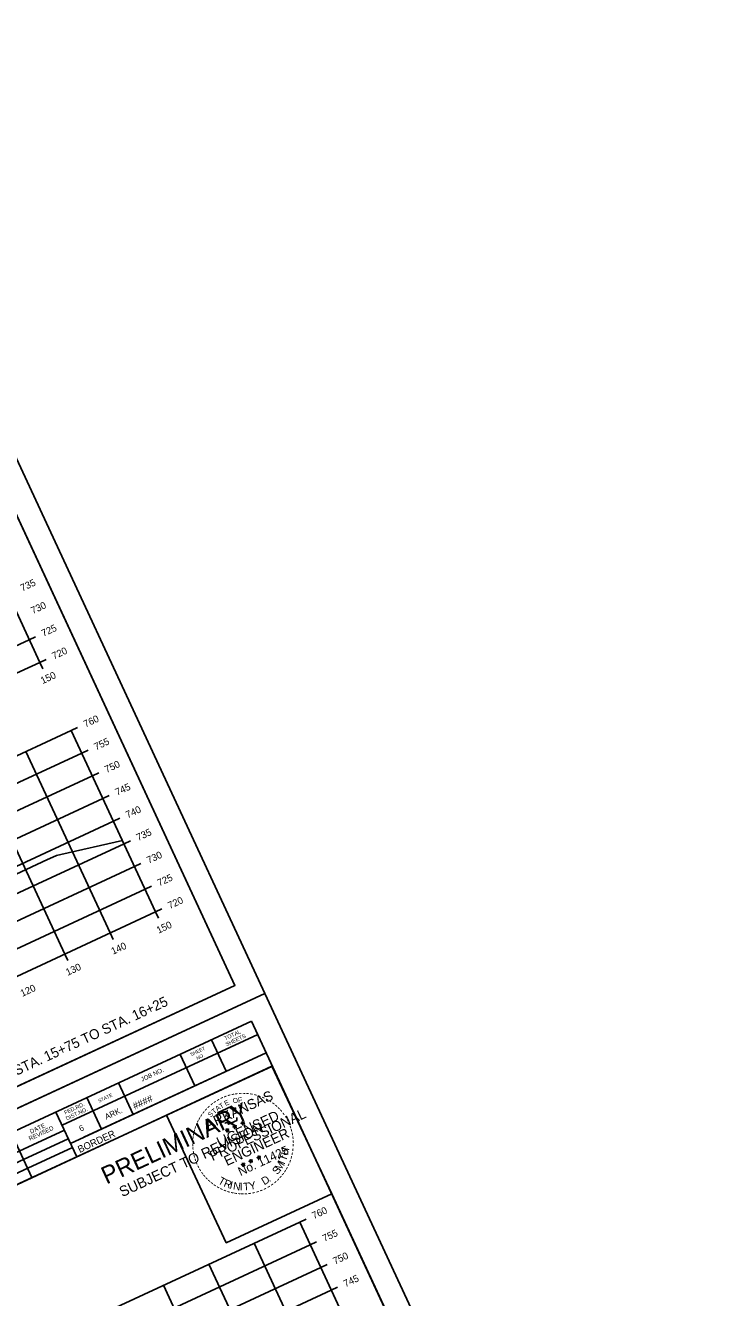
# Model space of a CAD drawing. Extents: x 1354696 to 1366163, y 660729 to 670380.
# Drawn here: x 1358937.5 to 1359075.2, y 666178.8 to 666433.1 of the extents above; entities that cross this region are included whole.
import ezdxf

# ---------------------------------------------------------------- set-up
doc = ezdxf.new("R2010")
doc.units = 0
for name, color, linetype in [('R_Axis', 7, 'Continuous'), ('R_Axis Annot', 7, 'Continuous'), ('R_Border', 7, 'Continuous'), ('R_Border PE', 7, 'Continuous'), ('R_Border Prem', 7, 'Continuous'), ('R_Draft', 7, 'Continuous'), ('R_Exist Surface', 7, 'Continuous'), ('R_Grid', 7, 'Continuous'), ('R_No Plot', 7, 'Continuous')]:
    doc.layers.add(name, color=color, linetype=linetype)

msp = doc.modelspace()

# ---------------------------------------------------------------- linework, layer by layer
at = {"layer": 'R_Axis'}
for p, q in [((1358940.34, 666305.76), (1358921.39, 666346.57)), ((1358939.5, 666310.88), (1358938.23, 666310.29)), ((1358668.23, 666179.43), (1358940.34, 666305.76)), ((1358941.61, 666306.35), (1358940.34, 666305.76)), ((1358940.93, 666304.49), (1358940.34, 666305.76)), ((1358947.92, 666292.74), (1358946.65, 666292.15)), ((1358963.5, 666255.87), (1358946.65, 666292.15)), ((1358950.03, 666288.21), (1358948.76, 666287.62)), ((1358952.14, 666283.67), (1358950.87, 666283.08)), ((1358954.24, 666279.14), (1358952.97, 666278.55)), ((1358956.35, 666274.6), (1358955.08, 666274.01)), ((1358958.45, 666270.07), (1358957.18, 666269.48)), ((1358960.56, 666265.53), (1358959.29, 666264.94)), ((1358962.66, 666261), (1358961.39, 666260.41)), ((1358964.77, 666256.46), (1358963.5, 666255.87)), ((1358691.39, 666129.54), (1358963.5, 666255.87)), ((1358964.09, 666254.6), (1358963.5, 666255.87)), ((1358955.02, 666250.39), (1358954.43, 666251.66)), ((1358945.95, 666246.18), (1358945.36, 666247.45)), ((1358993.55, 666194.48), (1358992.28, 666193.89)), ((1359009.12, 666157.61), (1358992.28, 666193.89)), ((1358995.65, 666189.94), (1358994.38, 666189.35)), ((1358997.76, 666185.41), (1358996.49, 666184.82)), ((1358999.86, 666180.87), (1358998.59, 666180.28))]:
    msp.add_line(p, q, dxfattribs=at)
at = {"layer": 'R_Border'}
for p, q in [((1358979.34, 666241.18), (1358892.82, 666427.53)), ((1358979.34, 666241.18), (1358692.56, 666108.03)), ((1358695.88, 666100.89), (1358982.66, 666234.03)), ((1359069.18, 666047.68), (1358982.66, 666234.03)), ((1358983.9, 666231.37), (1358944.8, 666213.22)), ((1358983.89, 666231.38), (1358983.89, 666231.38)), ((1358974.68, 666230.33), (1358977.6, 666224.03)), ((1358985.58, 666227.74), (1358946.49, 666209.59)), ((1358949.17, 666210.83), (1358985.58, 666227.74)), ((1358968.38, 666227.4), (1358971.3, 666221.11)), ((1358986.82, 666225.07), (1358930, 666198.69)), ((1358956.06, 666221.69), (1358958.99, 666215.39)), ((1358949.77, 666218.76), (1358952.69, 666212.47)), ((1358943.57, 666215.88), (1358947.73, 666206.92)), ((1358927.53, 666204.01), (1358945.26, 666212.24)), ((1358938.78, 666202.77), (1358934.62, 666211.73)), ((1358928.32, 666202.32), (1358946.04, 666210.55)), ((1358929.14, 666200.56), (1358946.86, 666208.79))]:
    msp.add_line(p, q, dxfattribs=at)
at = {"layer": 'R_Border PE'}
for p, q in [((1358979.34, 666212.94), (1358979.18, 666213.27)), ((1358979.18, 666213.27), (1358979.33, 666213.06)), ((1358979.18, 666213.27), (1358979.25, 666213.02)), ((1358979.6, 666213.18), (1358979.34, 666212.94)), ((1358979.6, 666213.18), (1358979.37, 666213.02)), ((1358979.6, 666213.18), (1358979.46, 666213)), ((1358980.58, 666213.62), (1358980.83, 666213.69)), ((1358980.58, 666213.62), (1358980.94, 666213.67)), ((1358980.58, 666213.62), (1358980.84, 666213.61)), ((1358980.94, 666213.67), (1358980.79, 666214)), ((1358980.79, 666214), (1358980.94, 666213.79)), ((1358980.79, 666214), (1358980.86, 666213.75)), ((1358980.87, 666213.31), (1358980.94, 666213.67)), ((1358980.87, 666213.31), (1358980.97, 666213.59)), ((1358980.87, 666213.31), (1358980.88, 666213.58)), ((1358981.21, 666213.91), (1358980.94, 666213.67)), ((1358981.26, 666213.49), (1358980.94, 666213.67)), ((1358981.21, 666213.91), (1358980.97, 666213.75)), ((1358981.26, 666213.49), (1358980.97, 666213.59)), ((1358981.26, 666213.49), (1358981.01, 666213.69)), ((1358981.21, 666213.91), (1358981.07, 666213.74)), ((1358977.46, 666212.19), (1358977.71, 666212.25)), ((1358977.46, 666212.19), (1358977.82, 666212.23)), ((1358977.46, 666212.19), (1358977.72, 666212.18)), ((1358977.82, 666212.23), (1358977.67, 666212.56)), ((1358977.67, 666212.56), (1358977.82, 666212.36)), ((1358977.67, 666212.56), (1358977.74, 666212.32)), ((1358977.75, 666211.87), (1358977.82, 666212.23)), ((1358977.75, 666211.87), (1358977.85, 666212.16)), ((1358977.75, 666211.87), (1358977.76, 666212.15)), ((1358978.09, 666212.48), (1358977.82, 666212.23)), ((1358978.14, 666212.05), (1358977.82, 666212.23)), ((1358978.09, 666212.48), (1358977.85, 666212.31)), ((1358978.14, 666212.05), (1358977.85, 666212.16)), ((1358978.14, 666212.05), (1358977.89, 666212.26)), ((1358978.09, 666212.48), (1358977.95, 666212.3)), ((1358978.97, 666212.89), (1358979.22, 666212.96)), ((1358978.97, 666212.89), (1358979.34, 666212.94)), ((1358978.97, 666212.89), (1358979.24, 666212.88)), ((1358979.27, 666212.58), (1358979.34, 666212.94)), ((1358979.27, 666212.58), (1358979.37, 666212.86)), ((1358979.27, 666212.58), (1358979.28, 666212.85)), ((1358979.65, 666212.76), (1358979.34, 666212.94)), ((1358979.65, 666212.76), (1358979.37, 666212.86)), ((1358979.65, 666212.76), (1358979.41, 666212.96)), ((1358981.01, 666205.36), (1358980.85, 666205.69)), ((1358980.85, 666205.69), (1358981, 666205.49)), ((1358980.85, 666205.69), (1358980.92, 666205.45)), ((1358981.27, 666205.61), (1358981.01, 666205.36)), ((1358981.27, 666205.61), (1358981.04, 666205.44)), ((1358981.27, 666205.61), (1358981.13, 666205.43)), ((1358982.16, 666206.02), (1358982.41, 666206.08)), ((1358982.16, 666206.02), (1358982.52, 666206.07)), ((1358982.16, 666206.02), (1358982.42, 666206.01)), ((1358982.52, 666206.07), (1358982.37, 666206.4)), ((1358982.37, 666206.4), (1358982.52, 666206.19)), ((1358982.37, 666206.4), (1358982.44, 666206.15)), ((1358982.45, 666205.7), (1358982.52, 666206.07)), ((1358982.45, 666205.7), (1358982.55, 666205.99)), ((1358982.45, 666205.7), (1358982.46, 666205.98)), ((1358982.79, 666206.31), (1358982.52, 666206.07)), ((1358982.84, 666205.89), (1358982.52, 666206.07)), ((1358982.79, 666206.31), (1358982.55, 666206.15)), ((1358982.84, 666205.89), (1358982.55, 666205.99)), ((1358982.84, 666205.89), (1358982.59, 666206.09)), ((1358982.79, 666206.31), (1358982.65, 666206.13)), ((1358983.76, 666206.75), (1358984.01, 666206.82)), ((1358983.76, 666206.75), (1358984.13, 666206.8)), ((1358983.76, 666206.75), (1358984.03, 666206.74)), ((1358984.13, 666206.8), (1358983.97, 666207.13)), ((1358983.97, 666207.13), (1358984.12, 666206.93)), ((1358983.97, 666207.13), (1358984.04, 666206.89)), ((1358984.06, 666206.44), (1358984.13, 666206.8)), ((1358984.06, 666206.44), (1358984.16, 666206.73)), ((1358984.06, 666206.44), (1358984.07, 666206.71)), ((1358984.4, 666207.05), (1358984.13, 666206.8)), ((1358984.45, 666206.62), (1358984.13, 666206.8)), ((1358984.4, 666207.05), (1358984.16, 666206.88)), ((1358984.45, 666206.62), (1358984.16, 666206.72)), ((1358984.45, 666206.62), (1358984.2, 666206.83)), ((1358984.4, 666207.05), (1358984.25, 666206.87)), ((1358980.64, 666205.32), (1358980.89, 666205.38)), ((1358980.64, 666205.32), (1358981.01, 666205.36)), ((1358980.64, 666205.32), (1358980.91, 666205.31)), ((1358980.94, 666205), (1358981.01, 666205.36)), ((1358980.94, 666205), (1358981.04, 666205.29)), ((1358980.94, 666205), (1358980.95, 666205.28)), ((1358981.32, 666205.18), (1358981.01, 666205.36)), ((1358981.32, 666205.18), (1358981.04, 666205.29)), ((1358981.32, 666205.18), (1358981.08, 666205.39))]:
    msp.add_line(p, q, dxfattribs=at)
for points in [[(1358979.43, 666216.36), (1358979.44, 666216.68), (1358978.83, 666216.37), (1358978.69, 666217.03), (1358975.86, 666215.72)], [(1358975.86, 666215.72), (1358976.45, 666215.08)], [(1358977.33, 666213.73), (1358977.37, 666213.65), (1358977.88, 666213.87), (1358978.03, 666213.42), (1358979.73, 666214.21), (1358979.69, 666214.78)], [(1358979.18, 666213.27), (1358979.65, 666212.76), (1358978.97, 666212.89), (1358979.6, 666213.18), (1358979.27, 666212.58), (1358979.18, 666213.27)], [(1358980.79, 666214), (1358981.26, 666213.49), (1358980.58, 666213.62), (1358981.21, 666213.91), (1358980.87, 666213.31), (1358980.79, 666214)], [(1358977.67, 666212.56), (1358978.14, 666212.05), (1358977.46, 666212.19), (1358978.09, 666212.48), (1358977.75, 666211.87), (1358977.67, 666212.56)], [(1358980.85, 666205.69), (1358981.32, 666205.18), (1358980.64, 666205.32), (1358981.27, 666205.61), (1358980.94, 666205), (1358980.85, 666205.69)], [(1358982.37, 666206.4), (1358982.84, 666205.89), (1358982.16, 666206.02), (1358982.79, 666206.31), (1358982.45, 666205.7), (1358982.37, 666206.4)], [(1358983.97, 666207.13), (1358984.45, 666206.62), (1358983.76, 666206.75), (1358984.4, 666207.05), (1358984.06, 666206.44), (1358983.97, 666207.13)]]:
    msp.add_lwpolyline(points, dxfattribs=at)
for centre, radius in [((1358980.94, 666213.67), 0.172), ((1358980.94, 666213.67), 0.145), ((1358980.94, 666213.67), 0.116), ((1358980.94, 666213.67), 0.0991), ((1358980.94, 666213.67), 0.0747), ((1358980.94, 666213.67), 0.0495), ((1358980.94, 666213.67), 0.0296), ((1358977.82, 666212.23), 0.172), ((1358977.82, 666212.23), 0.145), ((1358977.82, 666212.23), 0.116), ((1358977.82, 666212.23), 0.0991), ((1358977.82, 666212.23), 0.0747), ((1358977.82, 666212.23), 0.0495), ((1358977.82, 666212.23), 0.0296), ((1358979.34, 666212.93), 0.172), ((1358979.34, 666212.93), 0.145), ((1358979.34, 666212.93), 0.116), ((1358979.34, 666212.93), 0.0991), ((1358979.34, 666212.93), 0.0747), ((1358979.34, 666212.93), 0.0495), ((1358979.34, 666212.93), 0.0296), ((1358981.01, 666205.36), 0.172), ((1358982.52, 666206.06), 0.172), ((1358982.52, 666206.06), 0.145), ((1358982.52, 666206.06), 0.116), ((1358982.52, 666206.06), 0.0991), ((1358982.52, 666206.06), 0.0747), ((1358982.52, 666206.06), 0.0495), ((1358982.52, 666206.06), 0.0296), ((1358984.13, 666206.8), 0.172), ((1358984.13, 666206.8), 0.145), ((1358984.13, 666206.8), 0.116), ((1358984.13, 666206.8), 0.0991), ((1358984.13, 666206.8), 0.0747), ((1358984.13, 666206.8), 0.0495), ((1358984.13, 666206.8), 0.0296), ((1358981.01, 666205.36), 0.145), ((1358981.01, 666205.36), 0.116), ((1358981.01, 666205.36), 0.0991), ((1358981.01, 666205.36), 0.0747), ((1358981.01, 666205.36), 0.0495), ((1358981.01, 666205.36), 0.0296)]:
    msp.add_circle(centre, radius, dxfattribs=at)
at = {"layer": 'R_Exist Surface'}
msp.add_lwpolyline([(1358906.25, 666249.72), (1358939.75, 666265.33), (1358941.87, 666266.33), (1358942.93, 666266.81), (1358943.66, 666267.14), (1358944.56, 666267.37), (1358956.86, 666270.18)], dxfattribs=at)
at = {"layer": 'R_Grid'}
for p, q in [((1358940.34, 666305.76), (1358921.39, 666346.57)), ((1358666.13, 666183.96), (1358938.23, 666310.29)), ((1358668.23, 666179.43), (1358940.34, 666305.76)), ((1358674.55, 666165.82), (1358946.65, 666292.15)), ((1358963.5, 666255.87), (1358946.65, 666292.15)), ((1358676.66, 666161.29), (1358948.76, 666287.62)), ((1358954.43, 666251.66), (1358937.58, 666287.94)), ((1358678.76, 666156.75), (1358950.87, 666283.08)), ((1358945.36, 666247.45), (1358928.51, 666283.73)), ((1358680.87, 666152.22), (1358952.97, 666278.55)), ((1358682.97, 666147.68), (1358955.08, 666274.01)), ((1358685.08, 666143.15), (1358957.18, 666269.48)), ((1358687.18, 666138.61), (1358959.29, 666264.94)), ((1358689.29, 666134.08), (1358961.39, 666260.41)), ((1358691.39, 666129.54), (1358963.5, 666255.87)), ((1358720.17, 666067.56), (1358992.28, 666193.89)), ((1359009.12, 666157.61), (1358992.28, 666193.89)), ((1358722.28, 666063.02), (1358994.38, 666189.35)), ((1359000.05, 666153.4), (1358983.21, 666189.68)), ((1358990.98, 666149.19), (1358974.14, 666185.47)), ((1358724.38, 666058.49), (1358996.49, 666184.82)), ((1358726.49, 666053.95), (1358998.59, 666180.28)), ((1358981.91, 666144.98), (1358965.07, 666181.26))]:
    msp.add_line(p, q, dxfattribs=at)
at = {"layer": 'R_No Plot'}
for p, q in [((1358682.99, 666099.2), (1358985.33, 666239.57)), ((1358682.99, 666099.2), (1358985.33, 666239.57)), ((1358974.54, 666194.61), (1358974.54, 666194.61))]:
    msp.add_line(p, q, dxfattribs=at)
for points in [[(1358593.15, 666292.7), (1358895.49, 666433.07), (1358985.33, 666239.57), (1358682.98, 666099.2)], [(1358818.21, 666392.89), (1358836.01, 666401.15), (1358840.17, 666392.19), (1358854.78, 666398.98), (1358875.82, 666408.75), (1358887.79, 666383.26), (1358908.84, 666393.03), (1358979.34, 666241.18), (1358692.56, 666108.03), (1358606.04, 666294.39)], [(1358682.98, 666099.2), (1358985.33, 666239.57), (1359075.16, 666046.07), (1358772.82, 665905.7)], [(1358965.66, 666215.25), (1358986.71, 666225.02), (1358998.67, 666199.53), (1358977.62, 666189.76)], [(1358908.05, 666199.39), (1358925.84, 666207.65), (1358930, 666198.69), (1358944.62, 666205.48), (1358965.66, 666215.25), (1358977.62, 666189.76), (1358998.67, 666199.53), (1359069.18, 666047.68), (1358782.4, 665914.53), (1358695.88, 666100.89)]]:
    msp.add_lwpolyline(points, close=True, dxfattribs=at)

# ---------------------------------------------------------------- texts
at = {"layer": 'R_Axis Annot'}
for s, p in [('735', (1358936.86, 666319.91)), ('730', (1358938.96, 666315.37)), ('725', (1358941.07, 666310.84)), ('720', (1358943.17, 666306.3)), ('150', (1358940.91, 666301.39)), ('760', (1358949.49, 666292.7)), ('755', (1358951.59, 666288.16)), ('750', (1358953.7, 666283.63)), ('745', (1358955.81, 666279.09)), ('740', (1358957.91, 666274.56)), ('735', (1358960.02, 666270.02)), ('730', (1358962.12, 666265.49)), ('725', (1358964.23, 666260.95)), ('720', (1358966.33, 666256.42)), ('150', (1358964.07, 666251.51)), ('140', (1358955, 666247.3)), ('130', (1358945.93, 666243.09)), ('120', (1358936.86, 666238.88)), ('760', (1358995.11, 666194.43)), ('755', (1358997.22, 666189.9)), ('750', (1358999.32, 666185.36)), ('745', (1359001.43, 666180.83))]:
    msp.add_text(s, height=1.4, rotation=24.9042, dxfattribs=at).set_placement(p)
at = {"layer": 'R_Border'}
for s, height, p in [('TOTAL', 0.782, (1358977.43, 666230.19)), ('SHEETS', 0.782, (1358977.67, 666229)), ('SHEET', 0.684, (1358970.61, 666227.03)), ('NO.', 0.684, (1358971.81, 666226.28)), ('JOB NO.', 0.879, (1358960.8, 666221.94)), ('STATE', 0.684, (1358952.19, 666217.73)), ('####', 1.4, (1358959.31, 666216.35)), ('FED.RD.', 0.782, (1358945.45, 666215.34)), ('DIST.NO.', 0.782, (1358945.76, 666214.19)), ('ARK.', 1.172, (1358953.67, 666214.31)), ('DATE', 0.879, (1358938.6, 666211.52)), ('6', 1.17, (1358948.53, 666211.93)), ('REVISED', 0.879, (1358938.39, 666210.12)), ('BORDER', 1.4, (1358948.33, 666207.68))]:
    msp.add_text(s, height=height, rotation=24.9042, dxfattribs=at).set_placement(p)
at = {"layer": 'R_Border PE'}
for s, height, rotation, p in [('ARKANSAS', 2, 24.9042, (1358973.97, 666212.32)), ('-', 1.6, 30.801, (1358975.99, 666217.59)), ('-', 1.6, 25.0904, (1358976.66, 666217.98)), ('-', 1.6, 22.6472, (1358977.32, 666218.27)), ('E', 1, 25.7365, (1358977.49, 666217.07)), ('-', 1.6, 17.0659, (1358978.02, 666218.54)), ('-', 1.6, 12.1091, (1358978.72, 666218.73)), ('O', 1, 15.3557, (1358979.04, 666217.56)), ('-', 1.6, 7.2404, (1358979.36, 666218.86)), ('F', 1, 4.9748, (1358980, 666217.75)), ('-', 1.6, 2.7593, (1358980.12, 666218.97)), ('-', 1.6, 359.0253, (1358980.81, 666218.99)), ('-', 1.6, 354.5451, (1358981.45, 666218.98)), ('-', 1.6, 350.7668, (1358982.19, 666218.92)), ('-', 1.6, 345.4339, (1358982.92, 666218.79)), ('-', 1.6, 340.4828, (1358983.67, 666218.6)), ('-', 1.6, 334.7839, (1358984.42, 666218.34)), ('-', 1.6, 331.5563, (1358985.15, 666218.01)), ('-', 1.6, 53.696, (1358973.35, 666215.15)), ('-', 1.6, 49.2114, (1358973.79, 666215.71)), ('-', 1.6, 44.0802, (1358974.25, 666216.22)), ('S', 1, 46.4982, (1358974.51, 666214.74)), ('PROFESSIONAL', 2, 24.9042, (1358974.86, 666206.06)), ('-', 1.6, 38.5343, (1358974.83, 666216.75)), ('T', 1, 41.3078, (1358975.2, 666215.42)), ('-', 1.6, 35.1235, (1358975.38, 666217.18)), ('A', 1, 36.1173, (1358975.84, 666216)), ('LICENSED', 2, 24.9042, (1358976.26, 666208.81)), ('T', 1, 30.9269, (1358976.54, 666216.5)), ('-', 1.4, 328.5795, (1358985.83, 666217.7)), ('-', 1.6, 324.5725, (1358986.37, 666217.29)), ('-', 1.6, 319.567, (1358986.93, 666216.87)), ('-', 1.6, 315.477, (1358987.4, 666216.45)), ('-', 1.6, 310.0274, (1358987.86, 666216.03)), ('-', 1.6, 305.4535, (1358988.35, 666215.44)), ('-', 1.6, 67.8664, (1358972.12, 666212.86)), ('-', 1.6, 63.8548, (1358972.33, 666213.42)), ('-', 1.6, 61.1359, (1358972.61, 666213.96)), ('-', 1.6, 58.9677, (1358972.96, 666214.56)), ('DWB', 0.01, 24.9042, (1358980.93, 666213.66)), ('-', 1.6, 301.5003, (1358988.82, 666214.81)), ('-', 1.6, 299.2343, (1358989.18, 666214.18)), ('-', 1.6, 294.8448, (1358989.48, 666213.62)), ('-', 1.6, 82.9748, (1358971.54, 666210.32)), ('-', 1.6, 79.1366, (1358971.61, 666210.94)), ('-', 1.6, 75.5183, (1358971.75, 666211.63)), ('-', 1.6, 73.3272, (1358971.91, 666212.24)), ('ENGINEER', 2, 24.9042, (1358977.74, 666205.06)), ('DWB', 0.01, 24.9042, (1358977.81, 666212.22)), ('DWB', 0.01, 24.9042, (1358979.33, 666212.93)), ('-', 1.6, 288.4214, (1358989.74, 666213.01)), ('-', 1.6, 285.8995, (1358989.95, 666212.39)), ('-', 1.6, 280.6668, (1358990.14, 666211.72)), ('-', 1.6, 277.7723, (1358990.28, 666211)), ('-', 1.6, 92.6784, (1358971.54, 666208.97)), ('-', 1.6, 87.7755, (1358971.52, 666209.63)), ('-', 1.6, 97.2986, (1358971.61, 666208.31)), ('-', 1.6, 100.3651, (1358971.73, 666207.58)), ('No. 11425', 1.757, 24.9042, (1358980.46, 666203.06)), ('H', 1.54, 79.513, (1358989.96, 666207.17)), ('-', 1.6, 263.9754, (1358990.34, 666208.76)), ('-', 1.6, 272.7928, (1358990.36, 666210.29)), ('-', 1.6, 269.5239, (1358990.38, 666209.61)), ('-', 1.6, 106.1054, (1358971.91, 666206.87)), ('-', 1.6, 110.0905, (1358972.13, 666206.22)), ('-', 1.6, 113.9664, (1358972.4, 666205.57)), ('DWB', 0.01, 24.9042, (1358982.51, 666206.06)), ('DWB', 0.01, 24.9042, (1358984.12, 666206.79)), ('M', 1.54, 57.5605, (1358988.43, 666203.96)), ('I', 1.54, 67.0178, (1358989.24, 666205.27)), ('T', 1.54, 71.5486, (1358989.55, 666205.94)), ('-', 1.6, 245.9893, (1358989.65, 666205.91)), ('-', 1.6, 250.6695, (1358989.91, 666206.59)), ('-', 1.6, 256.1579, (1358990.1, 666207.31)), ('-', 1.6, 258.7494, (1358990.25, 666208)), ('-', 1.6, 119.1, (1358972.74, 666204.93)), ('-', 1.6, 123.8521, (1358973.09, 666204.35)), ('-', 1.6, 126.6191, (1358973.52, 666203.74)), ('-', 1.6, 130.362, (1358973.91, 666203.27)), ('T', 1.54, 330.9447, (1358975.84, 666201.68)), ('DWB', 0.01, 24.9042, (1358981, 666205.35)), ('D', 1.54, 31.3011, (1358985.2, 666201.21)), ('S', 1.54, 51.8354, (1358987.84, 666203.24)), ('-', 1.6, 229.1558, (1358988.23, 666203.58)), ('-', 1.6, 232.261, (1358988.67, 666204.13)), ('-', 1.6, 237.1533, (1358989.03, 666204.68)), ('-', 1.6, 240.6405, (1358989.35, 666205.25)), ('-', 1.6, 133.9916, (1358974.37, 666202.79)), ('-', 1.6, 138.9685, (1358974.86, 666202.36)), ('-', 1.6, 140.633, (1358975.39, 666201.92)), ('-', 1.6, 145.3513, (1358975.96, 666201.54)), ('-', 1.6, 150.7976, (1358976.57, 666201.2)), ('-', 1.6, 155.6223, (1358977.22, 666200.9)), ('R', 1.54, 338.9091, (1358976.97, 666201.05)), ('I', 1.54, 346.8735, (1358978.18, 666200.59)), ('N', 1.54, 351.4044, (1358978.89, 666200.4)), ('I', 1.54, 0.2645, (1358980.32, 666200.19)), ('T', 1.54, 4.7953, (1358981.06, 666200.17)), ('Y', 1.54, 12.7597, (1358982.35, 666200.28)), ('-', 1.6, 206.4959, (1358985.38, 666201.24)), ('-', 1.6, 210.7208, (1358986.09, 666201.65)), ('.', 1.54, 38.6683, (1358986.23, 666201.83)), ('-', 1.6, 216.1899, (1358986.7, 666202.08)), ('-', 1.6, 220.3785, (1358987.28, 666202.56)), ('-', 1.6, 225.6226, (1358987.79, 666203.07)), ('-', 1.6, 159.128, (1358977.92, 666200.62)), ('-', 1.6, 163.838, (1358978.59, 666200.42)), ('-', 1.6, 169.5505, (1358979.26, 666200.29)), ('-', 1.6, 172.9939, (1358979.93, 666200.19)), ('-', 1.6, 176.4746, (1358980.59, 666200.14)), ('-', 1.6, 179.5044, (1358981.17, 666200.13)), ('-', 1.6, 183.4654, (1358981.84, 666200.16)), ('-', 1.6, 187.7024, (1358982.55, 666200.26)), ('-', 1.6, 192.4597, (1358983.27, 666200.41)), ('-', 1.6, 198.0196, (1358984.02, 666200.64)), ('-', 1.6, 201.4224, (1358984.72, 666200.91))]:
    msp.add_text(s, height=height, rotation=rotation, dxfattribs=at).set_placement(p)
at = {"layer": 'R_Border Prem'}
for s, height, p in [('PRELIMINARY', 3.5, (1358953.67, 666201.37)), ('SUBJECT TO REVISION', 2.0751, (1358956.84, 666198.84)), ('DWB', 0.01, (1358953.57, 666203.36))]:
    msp.add_text(s, height=height, rotation=24.9042, dxfattribs=at).set_placement(p)
at = {"layer": 'R_Draft'}
msp.add_text('CROSS SECTION STA. 15+75 TO STA. 16+25', height=2, rotation=24.9042, dxfattribs=at).set_placement((1358914.93, 666213.48))

doc.saveas('drawing.dxf')
